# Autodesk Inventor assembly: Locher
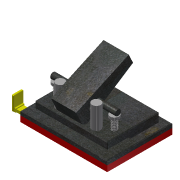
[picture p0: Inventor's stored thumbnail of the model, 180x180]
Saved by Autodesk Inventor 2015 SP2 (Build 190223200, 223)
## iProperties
Created: 2017-07
Part Number: Locher
Document SubType Name: Assembly
Designer: UR
Author: UR
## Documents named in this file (14)
- X:\Tresor_SSD\Arbeit\Unterricht\Stoff\Inventor\Locher 05 Version 2\Locher.iam
- X:\Tresor_SSD\Arbeit\Unterricht\Stoff\Inventor\Locher 05 Version 2\Grundplatte.ipt
- X:\Tresor_SSD\Arbeit\Unterricht\Stoff\Inventor\Locher 05 Version 2\Oberplatte.ipt
- X:\Tresor_SSD\Arbeit\Unterricht\Stoff\Inventor\Locher 05 Version 2\Saeule.ipt
- X:\Tresor_SSD\Arbeit\Unterricht\Stoff\Inventor\Locher 05 Version 2\Hebel.ipt
- X:\Tresor_SSD\Arbeit\Unterricht\Stoff\Inventor\Locher 05 Version 2\Lochpfeife.ipt
- X:\Tresor_SSD\Arbeit\Unterricht\Stoff\Inventor\Locher 05 Version 2\Hebelachse.ipt
- X:\Tresor_SSD\Arbeit\Unterricht\Stoff\Inventor\Locher 05 Version 2\Feder.ipt
- X:\Tresor_SSD\Arbeit\Unterricht\Stoff\Inventor\Locher 05 Version 2\Magnet.ipt
- X:\Tresor_SSD\Arbeit\Unterricht\Stoff\Inventor\Locher 05 Version 2\Boden-BG.iam
- X:\Tresor_SSD\Arbeit\Unterricht\Stoff\Inventor\Locher 05 Version 2\ISO 4762 - M4 x 12ISO.ipt
- X:\Tresor_SSD\Arbeit\Unterricht\Stoff\Inventor\Locher 05 Version 2\ISO 2338 - 4 h8 x 14 - B.ipt
- X:\Tresor_SSD\Arbeit\Unterricht\Stoff\Inventor\Locher 05 Version 2\ISO 4027 - M4 x 5ISO.ipt
- X:\Tresor_SSD\Arbeit\Unterricht\Stoff\Inventor\Locher 05 Version 2\Druckstift.ipt
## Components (22 placed, 13 different names)
1. Grundplatte:1 — Passend:33, Einfügen:7, Passend:34, Passend:35, Passend:36, Passend:37, Einfügen:10, Fluchtend:6, Passend:45, Passend:46, Einfügen:14, Einfügen:15, Einfügen:16, Einfügen:17, Einfügen:18, Passend:59
2. Oberplatte:1 — Passend:33, Passend:36, Passend:37, Passend:40, Einfügen:8, Einfügen:9, Passend:44, Einfügen:12, Einfügen:13, Fluchtend:7, Winkel:2
3. Saeule:1 — Einfügen:9, Passend:58
4. Saeule:2 — Einfügen:8, Passend:57, Tangential:1
5. Hebel:1 — Fluchtend:7, Passend:54, Passend:55, Passend:56, Passend:60
6. Druckstift:1 — Passend:55, Passend:56, Tangential:2, Tangential:3, Tangential:1
7. Lochpfeife:1 — Passend:14, Passend:20, Passend:44, Tangential:3, Tangential:4
8. Lochpfeife:2 — Passend:14, Passend:21, Passend:40, Tangential:5
9. Hebelachse:1 — Passend:57, Passend:58, Passend:59, Passend:60
10. ISO 2338 4 h8 x 14 - B:1 — Einfügen:18
11. ISO 2338 4 h8 x 14 - B:2 — Einfügen:10
12. Feder:1 — Passend:20, Tangential:4, Winkel:1, Winkel:2
13. Feder:2 — Passend:21, Tangential:5, Winkel:1
14. Magnet:1 — Einfügen:7
15. Boden-BG:1 [sub-assembly] — Fluchtend:6, Passend:45, Passend:46
16. ISO 4762 M4 x 12:1 — Einfügen:12
17. ISO 4762 M4 x 12:2 — Einfügen:13
18. ISO 4762 M4 x 12:3 — Einfügen:17
19. ISO 4762 M4 x 12:4 — Einfügen:16
20. ISO 4762 M4 x 12:5 — Einfügen:14
21. ISO 4762 M4 x 12:6 — Einfügen:15
22. ISO 4027 M4 x 5:1 — Passend:54, Tangential:2
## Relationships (39: Mate 19, Insert 11, Tangent 5, Flush 2, Angle 2)
- Passend:14 [Mate]: Lochpfeife:1 ↔ Lochpfeife:2
- Passend:20 [Mate]: Lochpfeife:1 ↔ Feder:1
- Passend:21 [Mate]: Lochpfeife:2 ↔ Feder:2
- Passend:33 [Mate]: Grundplatte:1 ↔ Oberplatte:1
- Einfügen:7 [Insert]: Grundplatte:1 ↔ Magnet:1
- Passend:34 [Mate]: Grundplatte:1
- Passend:35 [Mate]: Grundplatte:1
- Passend:36 [Mate]: Grundplatte:1 ↔ Oberplatte:1
- Passend:37 [Mate]: Grundplatte:1 ↔ Oberplatte:1
- Passend:40 [Mate]: Oberplatte:1 ↔ Lochpfeife:2
- Einfügen:8 [Insert]: Oberplatte:1 ↔ Saeule:2
- Einfügen:9 [Insert]: Oberplatte:1 ↔ Saeule:1
- Passend:44 [Mate]: Oberplatte:1 ↔ Lochpfeife:1
- Einfügen:10 [Insert]: Grundplatte:1 ↔ ISO 2338 4 h8 x 14 - B:2
- Fluchtend:6 [Flush]: Grundplatte:1 ↔ Boden-BG:1
- Passend:45 [Mate]: Grundplatte:1 ↔ Boden-BG:1
- Passend:46 [Mate]: Grundplatte:1 ↔ Boden-BG:1
- Einfügen:12 [Insert]: Oberplatte:1 ↔ ISO 4762 M4 x 12:1
- Einfügen:13 [Insert]: Oberplatte:1 ↔ ISO 4762 M4 x 12:2
- Einfügen:14 [Insert]: Grundplatte:1 ↔ ISO 4762 M4 x 12:5
- Einfügen:15 [Insert]: Grundplatte:1 ↔ ISO 4762 M4 x 12:6
- Einfügen:16 [Insert]: Grundplatte:1 ↔ ISO 4762 M4 x 12:4
- Einfügen:17 [Insert]: Grundplatte:1 ↔ ISO 4762 M4 x 12:3
- Fluchtend:7 [Flush]: Oberplatte:1 ↔ Hebel:1
- Passend:54 [Mate]: Hebel:1 ↔ ISO 4027 M4 x 5:1
- Passend:55 [Mate]: Hebel:1 ↔ Druckstift:1
- Passend:56 [Mate]: Hebel:1 ↔ Druckstift:1
- Tangential:2: Druckstift:1 ↔ ISO 4027 M4 x 5:1
- Einfügen:18 [Insert]: Grundplatte:1 ↔ ISO 2338 4 h8 x 14 - B:1
- Tangential:3: Druckstift:1 ↔ Lochpfeife:1
- Tangential:1: Saeule:2 ↔ Druckstift:1
- Passend:57 [Mate]: Saeule:2 ↔ Hebelachse:1
- Passend:58 [Mate]: Saeule:1 ↔ Hebelachse:1
- Passend:59 [Mate]: Grundplatte:1 ↔ Hebelachse:1
- Passend:60 [Mate]: Hebel:1 ↔ Hebelachse:1
- Tangential:4: Lochpfeife:1 ↔ Feder:1
- Tangential:5: Lochpfeife:2 ↔ Feder:2
- Winkel:1 [Angle]: Feder:1 ↔ Feder:2
- Winkel:2 [Angle]: Oberplatte:1 ↔ Feder:1
